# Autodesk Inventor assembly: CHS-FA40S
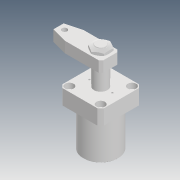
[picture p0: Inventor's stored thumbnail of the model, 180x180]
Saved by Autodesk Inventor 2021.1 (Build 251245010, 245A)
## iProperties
Created: 2019-04
Part Number: CHS-FA40S
Description: STEP AP203
Document SubType Name: Assembly
Designer: user
Title: chs-fa40s_asm.STEP
Revision Number: ÈÎºÎ
Sending System: SolidWorks 2017
Preprocessor: SwSTEP 2.0
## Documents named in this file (5)
- D:\Vault_2016\Projekty\Clamptek\Hydraulic\CHS\CHS-40\Inventor\CHS-FA40S\CHS-FA40S.iam
- D:\Vault_2016\Projekty\Clamptek\Hydraulic\CHS\CHS-40\Inventor\CHS-FA40S\CHS-40S-02_1.ipt
- D:\Vault_2016\Projekty\Clamptek\Hydraulic\CHS\CHS-40\Inventor\CHS-FA40S\CHS-40S-01_1.ipt
- D:\Vault_2016\Projekty\Clamptek\Hydraulic\CHS\CHS-40\Inventor\CHS-FA40S\M18_1.ipt
- D:\Vault_2016\Projekty\Clamptek\Hydraulic\CHS\CHS-40\Inventor\CHS-FA40S\CHS-FA40  BT.ipt
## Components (4 placed, 4 different names)
1. CHS-40S-02_1_1
2. CHS-40S-01_1_2
3. M18_1_3
4. CHS-FA40  BT_4
